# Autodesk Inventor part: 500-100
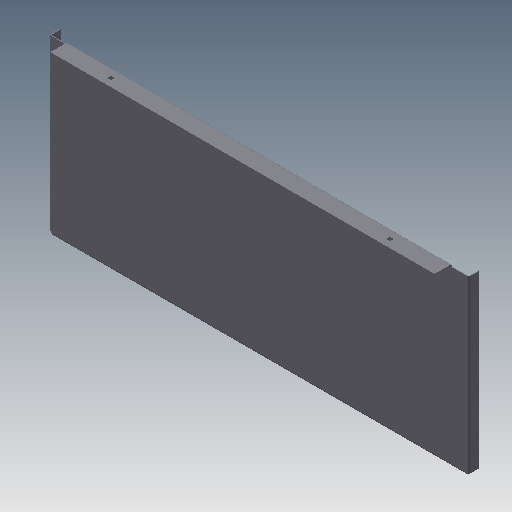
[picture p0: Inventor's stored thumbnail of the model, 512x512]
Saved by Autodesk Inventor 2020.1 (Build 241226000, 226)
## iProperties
Created: 2010-10
Part Number: 500-100
Document SubType Name: Konstrukcja blachowa
Designer: F.Stasiak
Density: 7.85 g/cm^3
Sheet Metal Rule: Blacha stalowa 2.5 mm/Okrągły
Material: St1203
Description: =Podstawa <DŁUGOŚĆ> x <SZEROKOŚĆ>
Mass: 13732.4 g
Surface Area: 14087.8 cm^2
Volume: 1749.35 cm^3
Appearance: Metal-Stal
Company: Fabian Stasiak CAD Consulting
Manager: www.cadconsulting.pl
d1: 497,500 mm
DŁUGOŚĆ: 1200
SZEROKOŚĆ: 500
Author: F.Stasiak
Subject: Zbiór ćwiczeń. Autodesk Inventor 2020. Kurs podstawowy
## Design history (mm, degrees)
node "Powierzchnia1"
  sketch "Szkic1"
    geometry: L1 (-597.5, -248.75)-(597.5, -248.75); L2 (597.5, -248.75)-(597.5, 248.75); L3 (597.5, 248.75)-(-597.5, 248.75); L4 (-597.5, 248.75)-(-597.5, -248.75); 3 further points
    constraints: 8 end point, 2 midpoint, 2 parallel, 1 horizontal, 1 horizontal alignment, 1 perpendicular, 1 vertical alignment
    dimensions: "d0" = 1195 distance of L3.end L2.end; "d1" = 497.5 distance of L2.end L1.end
node "Kołnierz3"
node "Kołnierz4"
sketch "Szkic7"
  geometry: L1 (0, -45)-(1095, -45) reference; L2 (1095, 0)-(1095, -45) reference; L3 (1095, 0)-(0, 0) reference; L4 (0, 0)-(0, -45) reference; L5 (0, -22.5)-(1095, -22.5); 3 further points
  constraints: 2 end point, 2 midpoint, 2 point on line
  dimensions: "d49" = 150 distance from line of L4 point (150, -22.5); "d50" = 150 distance from line of L2 point (945, -22.5) (= d49)
hole "Hole1" sketch "Szkic7" at (150, -22.5), (945, -22.5) diameter "d51" = 12; stored, may be unused: countersink angle "d55" = 90 deg, drill point angle "d57" = 118 deg; dims "d52" = 6, "d53" = 4, "d54" = 2, "d56" = 2.5 (= Grubość)
node "Bryła1"
feature "Płyta1" dims "d58" = 2.5 (= Grubość)
sketch "Szkic5"
  geometry: L1 (-1145, 0)-(-50, 0); L2 (-50, 0)-(-50, 50); L3 (-50, 50)-(-1145, 50); L4 (-1145, 50)-(-1145, 0)
  constraints: 8 end point
feature "Płyta4" dims "d27" = 2.5 (= SzerokośćGięciaPodcięcia), "d28" = 1.25 (= GłębokośćGięciaPodcięcia), "d29" = 100, "d30" = 2.5 (= PromieńGięcia), "d31" = 50, "d32" = 50, "d33" = 50, "d34" = 90 deg, "d35" = 2.5 (= PromieńGięcia), "d36" = 10 (= RozmiarPodcięciaNarożnika), "d37" = 2.5 (= Wielk_odstępu), "d38" = 2.5 (= Rozmiar_promienia_Jacobiego), "d58" = 2.5 (= Grubość), "OdstępPołączenia" = 0.01
feature "Gięcie3" dims "d27" = 2.5 (= SzerokośćGięciaPodcięcia), "d28" = 1.25 (= GłębokośćGięciaPodcięcia), "d29" = 100, "d30" = 2.5 (= PromieńGięcia), "d33" = 50, "d34" = 90 deg, "d35" = 2.5 (= PromieńGięcia), "d58" = 2.5 (= Grubość), "OdstępPołączenia" = 0.01
feature "Narożnik3" dims "d33" = 50, "d34" = 90 deg, "d36" = 10 (= RozmiarPodcięciaNarożnika), "d37" = 2.5 (= Wielk_odstępu), "d38" = 2.5 (= Rozmiar_promienia_Jacobiego)
sketch "Szkic6"
  geometry: L1 (0, -30)-(491.25, -30); L2 (491.25, -30)-(491.25, 0); 1 other entity
  constraints: 4 end point, 4 other
feature "Płyta5" dims "d39" = 2.5 (= SzerokośćGięciaPodcięcia), "d40" = 1.25 (= GłębokośćGięciaPodcięcia), "d41" = 5 (= MinimalnaPozostałość), "d42" = 2.5 (= PromieńGięcia), "d43" = 30, "d44" = 90 deg, "d45" = 2.5 (= PromieńGięcia), "d46" = 10 (= RozmiarPodcięciaNarożnika), "d47" = 2.5 (= Wielk_odstępu), "d48" = 2.5 (= Rozmiar_promienia_Jacobiego), "d58" = 2.5 (= Grubość), "OdstępPołączenia" = 0.01
feature "Gięcie4" dims "d39" = 2.5 (= SzerokośćGięciaPodcięcia), "d40" = 1.25 (= GłębokośćGięciaPodcięcia), "d41" = 5 (= MinimalnaPozostałość), "d42" = 2.5 (= PromieńGięcia), "d43" = 30, "d44" = 90 deg, "d45" = 2.5 (= PromieńGięcia), "d58" = 2.5 (= Grubość), "OdstępPołączenia" = 0.01
feature "Narożnik4" dims "d43" = 30, "d44" = 90 deg, "d46" = 10 (= RozmiarPodcięciaNarożnika), "d47" = 2.5 (= Wielk_odstępu), "d48" = 2.5 (= Rozmiar_promienia_Jacobiego)
node "Pętla rzutowana1"
other parameters: "Grubość" = 2.5 (derived), "WspółczynnikK" = 4.4, "PromieńGięcia" = 2.5 (= Grubość), "SzerokośćGięciaPodcięcia" = 2.5 (= Grubość), "GłębokośćGięciaPodcięcia" = 1.25 (= 0.5 x Grubość), "MinimalnaPozostałość" = 5 (= 2 x Grubość), "PromieńPrzejścia" = 2.5 (= PromieńGięcia), "Rozmiar_promienia_Jacobiego" = 2.5 (= PromieńGięcia), "Wielk_odstępu" = 2.5 (= Grubość), "d2" = 2.5 (= PromieńGięcia)
